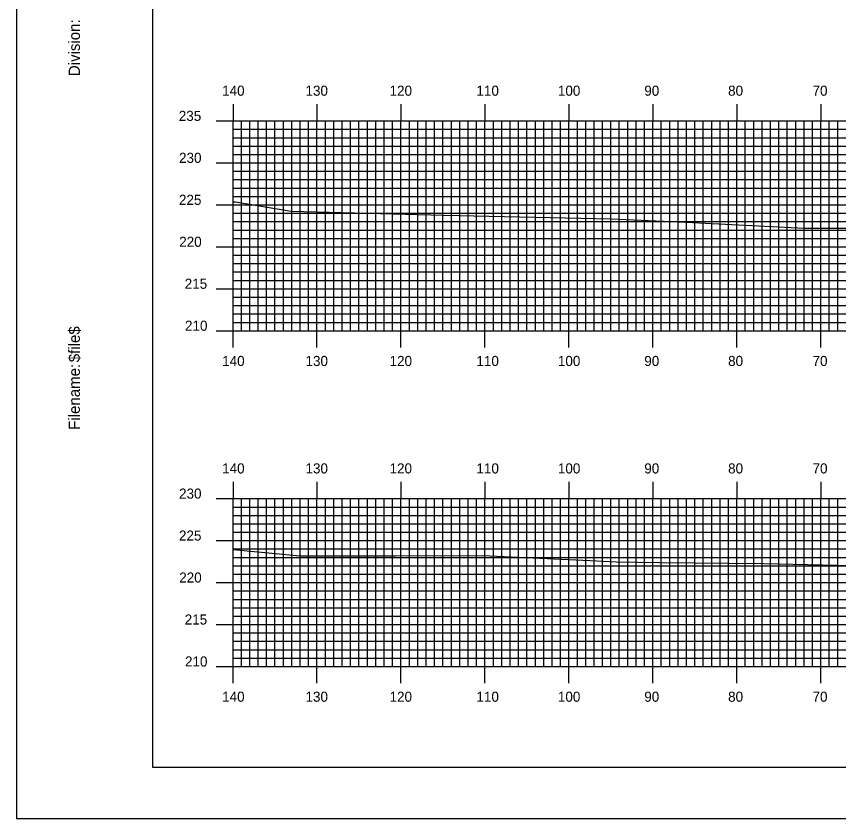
# Model space of a CAD drawing. Extents: x 1820031 to 1820374, y 442591 to 442811.
# Drawn here: x 1820030.9 to 1820128.8, y 442590.5 to 442686.1 of the extents above; entities that cross this region are included whole.
import ezdxf

# ---------------------------------------------------------------- set-up
doc = ezdxf.new("R2010")
doc.units = 0
for name, color, linetype in [('BORDER', 7, 'Continuous'), ('H_V ANNOTATION', 7, 'Continuous'), ('MAJOR', 7, 'Continuous'), ('MINOR', 7, 'Continuous'), ('PLOT BOUNDARY', 7, 'Continuous'), ('S_Roadway_Centerline', 7, 'Continuous')]:
    doc.layers.add(name, color=color, linetype=linetype)

msp = doc.modelspace()

# ---------------------------------------------------------------- linework, layer by layer
at = {"layer": 'BORDER'}
msp.add_lwpolyline([(1820047.091, 442596.665), (1820367.091, 442596.665), (1820367.091, 442806.665), (1820047.091, 442806.665)], close=True, dxfattribs=at)
at = {"layer": 'MAJOR'}
for p, q in [((1820056.691, 442675.669), (1820056.691, 442673.665)), ((1820066.691, 442675.669), (1820066.691, 442673.665)), ((1820076.691, 442675.669), (1820076.691, 442673.665)), ((1820086.691, 442675.669), (1820086.691, 442673.665)), ((1820096.691, 442675.669), (1820096.691, 442673.665)), ((1820106.691, 442675.669), (1820106.691, 442673.665)), ((1820116.691, 442675.669), (1820116.691, 442673.665)), ((1820126.691, 442675.669), (1820126.691, 442673.665)), ((1820054.687, 442673.665), (1820056.691, 442673.665)), ((1820056.691, 442673.665), (1820336.691, 442673.665)), ((1820056.691, 442648.665), (1820056.691, 442673.665)), ((1820056.691, 442648.665), (1820056.691, 442673.665)), ((1820056.691, 442673.665), (1820336.691, 442673.665)), ((1820066.691, 442648.665), (1820066.691, 442673.665)), ((1820076.691, 442648.665), (1820076.691, 442673.665)), ((1820086.691, 442648.665), (1820086.691, 442673.665)), ((1820096.691, 442648.665), (1820096.691, 442673.665)), ((1820106.691, 442648.665), (1820106.691, 442673.665)), ((1820116.691, 442648.665), (1820116.691, 442673.665)), ((1820126.691, 442648.665), (1820126.691, 442673.665)), ((1820054.687, 442668.665), (1820056.691, 442668.665)), ((1820056.691, 442668.665), (1820336.691, 442668.665)), ((1820054.687, 442663.665), (1820056.691, 442663.665)), ((1820056.691, 442663.665), (1820336.691, 442663.665)), ((1820054.687, 442658.665), (1820056.691, 442658.665)), ((1820056.691, 442658.665), (1820336.691, 442658.665)), ((1820054.687, 442653.665), (1820056.691, 442653.665)), ((1820056.691, 442653.665), (1820336.691, 442653.665)), ((1820054.687, 442648.665), (1820056.691, 442648.665)), ((1820056.691, 442648.665), (1820336.691, 442648.665)), ((1820056.691, 442648.665), (1820336.691, 442648.665)), ((1820056.691, 442646.661), (1820056.691, 442648.665)), ((1820066.691, 442646.661), (1820066.691, 442648.665)), ((1820076.691, 442646.661), (1820076.691, 442648.665)), ((1820086.691, 442646.661), (1820086.691, 442648.665)), ((1820096.691, 442646.661), (1820096.691, 442648.665)), ((1820106.691, 442646.661), (1820106.691, 442648.665)), ((1820116.691, 442646.661), (1820116.691, 442648.665)), ((1820126.691, 442646.661), (1820126.691, 442648.665)), ((1820056.691, 442630.669), (1820056.691, 442628.665)), ((1820066.691, 442630.669), (1820066.691, 442628.665)), ((1820076.691, 442630.669), (1820076.691, 442628.665)), ((1820086.691, 442630.669), (1820086.691, 442628.665)), ((1820096.691, 442630.669), (1820096.691, 442628.665)), ((1820106.691, 442630.669), (1820106.691, 442628.665)), ((1820116.691, 442630.669), (1820116.691, 442628.665)), ((1820126.691, 442630.669), (1820126.691, 442628.665)), ((1820054.687, 442628.665), (1820056.691, 442628.665)), ((1820056.691, 442628.665), (1820336.691, 442628.665)), ((1820056.691, 442608.665), (1820056.691, 442628.665)), ((1820056.691, 442608.665), (1820056.691, 442628.665)), ((1820056.691, 442628.665), (1820336.691, 442628.665)), ((1820066.691, 442608.665), (1820066.691, 442628.665)), ((1820076.691, 442608.665), (1820076.691, 442628.665)), ((1820086.691, 442608.665), (1820086.691, 442628.665)), ((1820096.691, 442608.665), (1820096.691, 442628.665)), ((1820106.691, 442608.665), (1820106.691, 442628.665)), ((1820116.691, 442608.665), (1820116.691, 442628.665)), ((1820126.691, 442608.665), (1820126.691, 442628.665)), ((1820054.687, 442623.665), (1820056.691, 442623.665)), ((1820056.691, 442623.665), (1820336.691, 442623.665)), ((1820054.687, 442618.665), (1820056.691, 442618.665)), ((1820056.691, 442618.665), (1820336.691, 442618.665)), ((1820054.687, 442613.665), (1820056.691, 442613.665)), ((1820056.691, 442613.665), (1820336.691, 442613.665)), ((1820054.687, 442608.665), (1820056.691, 442608.665)), ((1820056.691, 442608.665), (1820336.691, 442608.665)), ((1820056.691, 442608.665), (1820336.691, 442608.665)), ((1820056.691, 442606.661), (1820056.691, 442608.665)), ((1820066.691, 442606.661), (1820066.691, 442608.665)), ((1820076.691, 442606.661), (1820076.691, 442608.665)), ((1820086.691, 442606.661), (1820086.691, 442608.665)), ((1820096.691, 442606.661), (1820096.691, 442608.665)), ((1820106.691, 442606.661), (1820106.691, 442608.665)), ((1820116.691, 442606.661), (1820116.691, 442608.665)), ((1820126.691, 442606.661), (1820126.691, 442608.665))]:
    msp.add_line(p, q, dxfattribs=at)
at = {"layer": 'MINOR'}
for p, q in [((1820057.691, 442648.665), (1820057.691, 442673.665)), ((1820058.691, 442648.665), (1820058.691, 442673.665)), ((1820059.691, 442648.665), (1820059.691, 442673.665)), ((1820060.691, 442648.665), (1820060.691, 442673.665)), ((1820061.691, 442648.665), (1820061.691, 442673.665)), ((1820062.691, 442648.665), (1820062.691, 442673.665)), ((1820063.691, 442648.665), (1820063.691, 442673.665)), ((1820064.691, 442648.665), (1820064.691, 442673.665)), ((1820065.691, 442648.665), (1820065.691, 442673.665)), ((1820067.691, 442648.665), (1820067.691, 442673.665)), ((1820068.691, 442648.665), (1820068.691, 442673.665)), ((1820069.691, 442648.665), (1820069.691, 442673.665)), ((1820070.691, 442648.665), (1820070.691, 442673.665)), ((1820071.691, 442648.665), (1820071.691, 442673.665)), ((1820072.691, 442648.665), (1820072.691, 442673.665)), ((1820073.691, 442648.665), (1820073.691, 442673.665)), ((1820074.691, 442648.665), (1820074.691, 442673.665)), ((1820075.691, 442648.665), (1820075.691, 442673.665)), ((1820077.691, 442648.665), (1820077.691, 442673.665)), ((1820078.691, 442648.665), (1820078.691, 442673.665)), ((1820079.691, 442648.665), (1820079.691, 442673.665)), ((1820080.691, 442648.665), (1820080.691, 442673.665)), ((1820081.691, 442648.665), (1820081.691, 442673.665)), ((1820082.691, 442648.665), (1820082.691, 442673.665)), ((1820083.691, 442648.665), (1820083.691, 442673.665)), ((1820084.691, 442648.665), (1820084.691, 442673.665)), ((1820085.691, 442648.665), (1820085.691, 442673.665)), ((1820087.691, 442648.665), (1820087.691, 442673.665)), ((1820088.691, 442648.665), (1820088.691, 442673.665)), ((1820089.691, 442648.665), (1820089.691, 442673.665)), ((1820090.691, 442648.665), (1820090.691, 442673.665)), ((1820091.691, 442648.665), (1820091.691, 442673.665)), ((1820092.691, 442648.665), (1820092.691, 442673.665)), ((1820093.691, 442648.665), (1820093.691, 442673.665)), ((1820094.691, 442648.665), (1820094.691, 442673.665)), ((1820095.691, 442648.665), (1820095.691, 442673.665)), ((1820097.691, 442648.665), (1820097.691, 442673.665)), ((1820098.691, 442648.665), (1820098.691, 442673.665)), ((1820099.691, 442648.665), (1820099.691, 442673.665)), ((1820100.691, 442648.665), (1820100.691, 442673.665)), ((1820101.691, 442648.665), (1820101.691, 442673.665)), ((1820102.691, 442648.665), (1820102.691, 442673.665)), ((1820103.691, 442648.665), (1820103.691, 442673.665)), ((1820104.691, 442648.665), (1820104.691, 442673.665)), ((1820105.691, 442648.665), (1820105.691, 442673.665)), ((1820107.691, 442648.665), (1820107.691, 442673.665)), ((1820108.691, 442648.665), (1820108.691, 442673.665)), ((1820109.691, 442648.665), (1820109.691, 442673.665)), ((1820110.691, 442648.665), (1820110.691, 442673.665)), ((1820111.691, 442648.665), (1820111.691, 442673.665)), ((1820112.691, 442648.665), (1820112.691, 442673.665)), ((1820113.691, 442648.665), (1820113.691, 442673.665)), ((1820114.691, 442648.665), (1820114.691, 442673.665)), ((1820115.691, 442648.665), (1820115.691, 442673.665)), ((1820117.691, 442648.665), (1820117.691, 442673.665)), ((1820118.691, 442648.665), (1820118.691, 442673.665)), ((1820119.691, 442648.665), (1820119.691, 442673.665)), ((1820120.691, 442648.665), (1820120.691, 442673.665)), ((1820121.691, 442648.665), (1820121.691, 442673.665)), ((1820122.691, 442648.665), (1820122.691, 442673.665)), ((1820123.691, 442648.665), (1820123.691, 442673.665)), ((1820124.691, 442648.665), (1820124.691, 442673.665)), ((1820125.691, 442648.665), (1820125.691, 442673.665)), ((1820127.691, 442648.665), (1820127.691, 442673.665)), ((1820128.691, 442648.665), (1820128.691, 442673.665)), ((1820056.691, 442672.665), (1820336.691, 442672.665)), ((1820056.691, 442672.665), (1820058.695, 442672.665)), ((1820056.691, 442671.665), (1820336.691, 442671.665)), ((1820056.691, 442671.665), (1820058.695, 442671.665)), ((1820056.691, 442670.665), (1820336.691, 442670.665)), ((1820056.691, 442670.665), (1820058.695, 442670.665)), ((1820056.691, 442669.665), (1820336.691, 442669.665)), ((1820056.691, 442669.665), (1820058.695, 442669.665)), ((1820056.691, 442667.665), (1820336.691, 442667.665)), ((1820056.691, 442667.665), (1820058.695, 442667.665)), ((1820056.691, 442666.665), (1820336.691, 442666.665)), ((1820056.691, 442666.665), (1820058.695, 442666.665)), ((1820056.691, 442665.665), (1820336.691, 442665.665)), ((1820056.691, 442665.665), (1820058.695, 442665.665)), ((1820056.691, 442664.665), (1820336.691, 442664.665)), ((1820056.691, 442664.665), (1820058.695, 442664.665)), ((1820056.691, 442662.665), (1820336.691, 442662.665)), ((1820056.691, 442662.665), (1820058.695, 442662.665)), ((1820056.691, 442661.665), (1820336.691, 442661.665)), ((1820056.691, 442661.665), (1820058.695, 442661.665)), ((1820056.691, 442660.665), (1820336.691, 442660.665)), ((1820056.691, 442660.665), (1820058.695, 442660.665)), ((1820056.691, 442659.665), (1820336.691, 442659.665)), ((1820056.691, 442659.665), (1820058.695, 442659.665)), ((1820056.691, 442657.665), (1820336.691, 442657.665)), ((1820056.691, 442657.665), (1820058.695, 442657.665)), ((1820056.691, 442656.665), (1820336.691, 442656.665)), ((1820056.691, 442656.665), (1820058.695, 442656.665)), ((1820056.691, 442655.665), (1820336.691, 442655.665)), ((1820056.691, 442655.665), (1820058.695, 442655.665)), ((1820056.691, 442654.665), (1820336.691, 442654.665)), ((1820056.691, 442654.665), (1820058.695, 442654.665)), ((1820056.691, 442652.665), (1820336.691, 442652.665)), ((1820056.691, 442652.665), (1820058.695, 442652.665)), ((1820056.691, 442651.665), (1820336.691, 442651.665)), ((1820056.691, 442651.665), (1820058.695, 442651.665)), ((1820056.691, 442650.665), (1820336.691, 442650.665)), ((1820056.691, 442650.665), (1820058.695, 442650.665)), ((1820056.691, 442649.665), (1820336.691, 442649.665)), ((1820056.691, 442649.665), (1820058.695, 442649.665)), ((1820057.691, 442608.665), (1820057.691, 442628.665)), ((1820058.691, 442608.665), (1820058.691, 442628.665)), ((1820059.691, 442608.665), (1820059.691, 442628.665)), ((1820060.691, 442608.665), (1820060.691, 442628.665)), ((1820061.691, 442608.665), (1820061.691, 442628.665)), ((1820062.691, 442608.665), (1820062.691, 442628.665)), ((1820063.691, 442608.665), (1820063.691, 442628.665)), ((1820064.691, 442608.665), (1820064.691, 442628.665)), ((1820065.691, 442608.665), (1820065.691, 442628.665)), ((1820067.691, 442608.665), (1820067.691, 442628.665)), ((1820068.691, 442608.665), (1820068.691, 442628.665)), ((1820069.691, 442608.665), (1820069.691, 442628.665)), ((1820070.691, 442608.665), (1820070.691, 442628.665)), ((1820071.691, 442608.665), (1820071.691, 442628.665)), ((1820072.691, 442608.665), (1820072.691, 442628.665)), ((1820073.691, 442608.665), (1820073.691, 442628.665)), ((1820074.691, 442608.665), (1820074.691, 442628.665)), ((1820075.691, 442608.665), (1820075.691, 442628.665)), ((1820077.691, 442608.665), (1820077.691, 442628.665)), ((1820078.691, 442608.665), (1820078.691, 442628.665)), ((1820079.691, 442608.665), (1820079.691, 442628.665)), ((1820080.691, 442608.665), (1820080.691, 442628.665)), ((1820081.691, 442608.665), (1820081.691, 442628.665)), ((1820082.691, 442608.665), (1820082.691, 442628.665)), ((1820083.691, 442608.665), (1820083.691, 442628.665)), ((1820084.691, 442608.665), (1820084.691, 442628.665)), ((1820085.691, 442608.665), (1820085.691, 442628.665)), ((1820087.691, 442608.665), (1820087.691, 442628.665)), ((1820088.691, 442608.665), (1820088.691, 442628.665)), ((1820089.691, 442608.665), (1820089.691, 442628.665)), ((1820090.691, 442608.665), (1820090.691, 442628.665)), ((1820091.691, 442608.665), (1820091.691, 442628.665)), ((1820092.691, 442608.665), (1820092.691, 442628.665)), ((1820093.691, 442608.665), (1820093.691, 442628.665)), ((1820094.691, 442608.665), (1820094.691, 442628.665)), ((1820095.691, 442608.665), (1820095.691, 442628.665)), ((1820097.691, 442608.665), (1820097.691, 442628.665)), ((1820098.691, 442608.665), (1820098.691, 442628.665)), ((1820099.691, 442608.665), (1820099.691, 442628.665)), ((1820100.691, 442608.665), (1820100.691, 442628.665)), ((1820101.691, 442608.665), (1820101.691, 442628.665)), ((1820102.691, 442608.665), (1820102.691, 442628.665)), ((1820103.691, 442608.665), (1820103.691, 442628.665)), ((1820104.691, 442608.665), (1820104.691, 442628.665)), ((1820105.691, 442608.665), (1820105.691, 442628.665)), ((1820107.691, 442608.665), (1820107.691, 442628.665)), ((1820108.691, 442608.665), (1820108.691, 442628.665)), ((1820109.691, 442608.665), (1820109.691, 442628.665)), ((1820110.691, 442608.665), (1820110.691, 442628.665)), ((1820111.691, 442608.665), (1820111.691, 442628.665)), ((1820112.691, 442608.665), (1820112.691, 442628.665)), ((1820113.691, 442608.665), (1820113.691, 442628.665)), ((1820114.691, 442608.665), (1820114.691, 442628.665)), ((1820115.691, 442608.665), (1820115.691, 442628.665)), ((1820117.691, 442608.665), (1820117.691, 442628.665)), ((1820118.691, 442608.665), (1820118.691, 442628.665)), ((1820119.691, 442608.665), (1820119.691, 442628.665)), ((1820120.691, 442608.665), (1820120.691, 442628.665)), ((1820121.691, 442608.665), (1820121.691, 442628.665)), ((1820122.691, 442608.665), (1820122.691, 442628.665)), ((1820123.691, 442608.665), (1820123.691, 442628.665)), ((1820124.691, 442608.665), (1820124.691, 442628.665)), ((1820125.691, 442608.665), (1820125.691, 442628.665)), ((1820127.691, 442608.665), (1820127.691, 442628.665)), ((1820128.691, 442608.665), (1820128.691, 442628.665)), ((1820056.691, 442627.665), (1820336.691, 442627.665)), ((1820056.691, 442627.665), (1820058.695, 442627.665)), ((1820056.691, 442626.665), (1820336.691, 442626.665)), ((1820056.691, 442626.665), (1820058.695, 442626.665)), ((1820056.691, 442625.665), (1820336.691, 442625.665)), ((1820056.691, 442625.665), (1820058.695, 442625.665)), ((1820056.691, 442624.665), (1820336.691, 442624.665)), ((1820056.691, 442624.665), (1820058.695, 442624.665)), ((1820056.691, 442622.665), (1820336.691, 442622.665)), ((1820056.691, 442622.665), (1820058.695, 442622.665)), ((1820056.691, 442621.665), (1820336.691, 442621.665)), ((1820056.691, 442621.665), (1820058.695, 442621.665)), ((1820056.691, 442620.665), (1820336.691, 442620.665)), ((1820056.691, 442620.665), (1820058.695, 442620.665)), ((1820056.691, 442619.665), (1820336.691, 442619.665)), ((1820056.691, 442619.665), (1820058.695, 442619.665)), ((1820056.691, 442617.665), (1820336.691, 442617.665)), ((1820056.691, 442617.665), (1820058.695, 442617.665)), ((1820056.691, 442616.665), (1820336.691, 442616.665)), ((1820056.691, 442616.665), (1820058.695, 442616.665)), ((1820056.691, 442615.665), (1820336.691, 442615.665)), ((1820056.691, 442615.665), (1820058.695, 442615.665)), ((1820056.691, 442614.665), (1820336.691, 442614.665)), ((1820056.691, 442614.665), (1820058.695, 442614.665)), ((1820056.691, 442612.665), (1820336.691, 442612.665)), ((1820056.691, 442612.665), (1820058.695, 442612.665)), ((1820056.691, 442611.665), (1820336.691, 442611.665)), ((1820056.691, 442611.665), (1820058.695, 442611.665)), ((1820056.691, 442610.665), (1820336.691, 442610.665)), ((1820056.691, 442610.665), (1820058.695, 442610.665)), ((1820056.691, 442609.665), (1820336.691, 442609.665)), ((1820056.691, 442609.665), (1820058.695, 442609.665))]:
    msp.add_line(p, q, dxfattribs=at)
at = {"layer": 'PLOT BOUNDARY'}
msp.add_lwpolyline([(1820030.904, 442590.547), (1820370.904, 442590.547), (1820370.904, 442810.547), (1820030.904, 442810.547)], close=True, dxfattribs=at)
at = {"layer": 'S_Roadway_Centerline'}
for points in [[(1820056.691, 442664.029), (1820056.995, 442664.034), (1820063.602, 442662.911), (1820081.743, 442662.447), (1820101.723, 442662.016), (1820110.609, 442661.608), (1820124.722, 442660.905), (1820130.069, 442660.883), (1820140.732, 442660.939), (1820148.977, 442660.464), (1820155.715, 442660.066), (1820160.35, 442659.819), (1820174.748, 442659.571), (1820182.839, 442659.24), (1820191.56, 442658.576), (1820196.321, 442658.425), (1820208.928, 442657.642), (1820223.998, 442657.833), (1820229.939, 442657.561), (1820241.992, 442656.622), (1820249.223, 442656.314), (1820259.819, 442656.416)], [(1820056.691, 442622.611), (1820064.685, 442621.848), (1820076.039, 442621.848), (1820086.411, 442621.895), (1820099.235, 442621.295), (1820102.307, 442621.144), (1820107.458, 442621.06), (1820119.884, 442620.929), (1820126.827, 442620.757), (1820136.395, 442620.574), (1820138.18, 442620.482), (1820181.731, 442617.927), (1820187.68, 442617.591), (1820190.87, 442617.603), (1820193.688, 442617.403), (1820212.258, 442616.703), (1820222.129, 442616.122), (1820232.293, 442615.879), (1820248.056, 442615.293), (1820255.722, 442615.201)]]:
    msp.add_lwpolyline(points, dxfattribs=at)

# ---------------------------------------------------------------- texts
at = {"layer": 'BORDER'}
for s, p in [('Division:', (1820038.461, 442678.997)), ('$file$', (1820038.461, 442644.916)), ('Filename:', (1820038.461, 442636.862))]:
    msp.add_text(s, height=1.3392, rotation=90, dxfattribs=at).set_placement(p)
at = {"layer": 'H_V ANNOTATION'}
for s, p in [('140', (1820055.396, 442676.665)), ('130', (1820065.321, 442676.665)), ('120', (1820075.331, 442676.665)), ('110', (1820085.674, 442676.665)), ('100', (1820095.374, 442676.665)), ('90', (1820105.663, 442676.665)), ('80', (1820115.642, 442676.665)), ('70', (1820125.695, 442676.665)), ('235', (1820050.233, 442673.665)), ('230', (1820050.265, 442668.665)), ('225', (1820050.254, 442663.665)), ('220', (1820050.286, 442658.665)), ('215', (1820050.94, 442653.665)), ('210', (1820050.972, 442648.665)), ('140', (1820055.396, 442644.465)), ('130', (1820065.321, 442644.465)), ('120', (1820075.331, 442644.465)), ('110', (1820085.674, 442644.465)), ('100', (1820095.374, 442644.465)), ('90', (1820105.663, 442644.465)), ('80', (1820115.642, 442644.465)), ('70', (1820125.695, 442644.465)), ('140', (1820055.396, 442631.665)), ('130', (1820065.321, 442631.665)), ('120', (1820075.331, 442631.665)), ('110', (1820085.674, 442631.665)), ('100', (1820095.374, 442631.665)), ('90', (1820105.663, 442631.665)), ('80', (1820115.642, 442631.665)), ('70', (1820125.695, 442631.665)), ('230', (1820050.265, 442628.665)), ('225', (1820050.254, 442623.665)), ('220', (1820050.286, 442618.665)), ('215', (1820050.94, 442613.665)), ('210', (1820050.972, 442608.665)), ('140', (1820055.396, 442604.465)), ('130', (1820065.321, 442604.465)), ('120', (1820075.331, 442604.465)), ('110', (1820085.674, 442604.465)), ('100', (1820095.374, 442604.465)), ('90', (1820105.663, 442604.465)), ('80', (1820115.642, 442604.465)), ('70', (1820125.695, 442604.465))]:
    msp.add_text(s, height=1.2, dxfattribs=at).set_placement(p)
at = {"layer": 'MAJOR'}
for p in [(1820056.682, 442648.665), (1820056.682, 442608.665)]:
    msp.add_text('-', height=0.012, dxfattribs=at).set_placement(p)

doc.saveas('drawing.dxf')
